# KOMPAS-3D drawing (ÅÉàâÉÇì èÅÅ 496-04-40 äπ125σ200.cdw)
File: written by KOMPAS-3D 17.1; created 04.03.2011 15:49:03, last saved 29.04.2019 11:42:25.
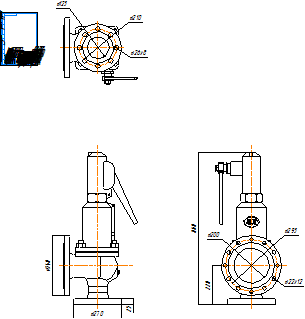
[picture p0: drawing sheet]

Sheet 1: A4, portrait

Title block, sheet 1: name: Прегран Ду 125х200; material: Внимание! Данный продукт является объектом авторского права ООО «Торговый Дом АДЛ». / Запрещается изменение, копирование, распространение / (в том числе путем копирования на другие сайты и ресурсы в Интернете) / или любое иное использование информации и объектов без предварительного / согласия правообладателя (ООО «Торговый Дом АДЛ»).; scale: 1:1; sheets: 1; organisation: ООО "Торговый дом АДЛ"; sheet format: A4; stored path: C:\Users\tra\Desktop\2д чертежи\Предохранительные клапаны ПРЕГРАН\ПРЕГРАН 496\ПРЕГРАН КПП 496-04-40\KOMPAS 2D\Прегран Ду 125х200.cdw

Views: Спереди 1, Проекционный вид 2, Проекционный вид 3
Dimensions and other numbers on the sheet: 270; 340; 220; 860; 295; 22; 200; 210; 125; 25; 26; 1:1; 1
